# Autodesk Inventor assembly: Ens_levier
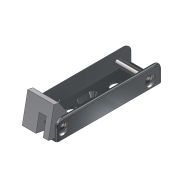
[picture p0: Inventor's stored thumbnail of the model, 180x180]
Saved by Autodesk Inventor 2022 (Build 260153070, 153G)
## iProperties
Created: 2018-06
Part Number: Ens_levier
Material: Générique
Document SubType Name: Assembly
Designer: Fabian Perrée
Mass: 50.2616 g
Surface Area: 113.894 cm^2
Volume: 10.4343 cm^3
Author: Fabian Perrée
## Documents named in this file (6)
- C:\Users\Fabian\Google Drive\01_Giup\01_Clients\07_ENI\Manuscrit\Fichiers_exercice\Chapitre_06\Exercice_de_fin_de_chapitre\Exercice_fin_de_chapitre_solution\Ens_levier.iam
- C:\Users\Fabian\Google Drive\01_Giup\01_Clients\07_ENI\Manuscrit\Fichiers_exercice\Chapitre_06\Exercice_de_fin_de_chapitre\Composants\Levier.ipt
- C:\Users\Fabian\Google Drive\01_Giup\01_Clients\07_ENI\Manuscrit\Fichiers_exercice\Chapitre_06\Exercice_de_fin_de_chapitre\Composants\Butee.ipt
- C:\Users\Fabian\Google Drive\01_Giup\01_Clients\07_ENI\Manuscrit\Fichiers_exercice\Chapitre_06\Exercice_de_fin_de_chapitre\Composants\Axe_25.ipt
- C:\Users\Fabian\Google Drive\01_Giup\01_Clients\07_ENI\Manuscrit\Fichiers_exercice\Chapitre_06\Exercice_de_fin_de_chapitre\Composants\Axe_28.ipt
- C:\Users\Fabian\Google Drive\01_Giup\01_Clients\07_ENI\Manuscrit\Fichiers_exercice\Chapitre_06\Exercice_de_fin_de_chapitre\Composants\Ressort de torsion1.iam
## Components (5 placed, 5 different names)
1. Levier:1 — Placage:4, Logement:2
2. Butee:1 — Tangente:1, Tangente:2
3. Axe_25:1 — Placage:3
4. Axe_28:1 — Logement:2
5. Ressort de torsion:1 [sub-assembly] — Placage:3, Tangente:1, Tangente:2, Placage:4
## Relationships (5: Mate 2, Tangent 2, Insert 1)
- Placage:3 [Mate]: Axe_25:1 ↔ Ressort de torsion:1
- Tangente:1: Butee:1 ↔ Ressort de torsion:1
- Tangente:2: Butee:1 ↔ Ressort de torsion:1
- Placage:4 [Mate]: Levier:1 ↔ Ressort de torsion:1
- Logement:2 [Insert]: Levier:1 ↔ Axe_28:1
